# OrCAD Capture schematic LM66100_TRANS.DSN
size E; title: LM66100: 5.5-V, 1.5-A 79mOhm, Low IQ Ideal Diode With; rev: 1.0; note: Datasheet: SLVSEZ8A     EVM: SLVUBL9; note: Input Polarity Protection
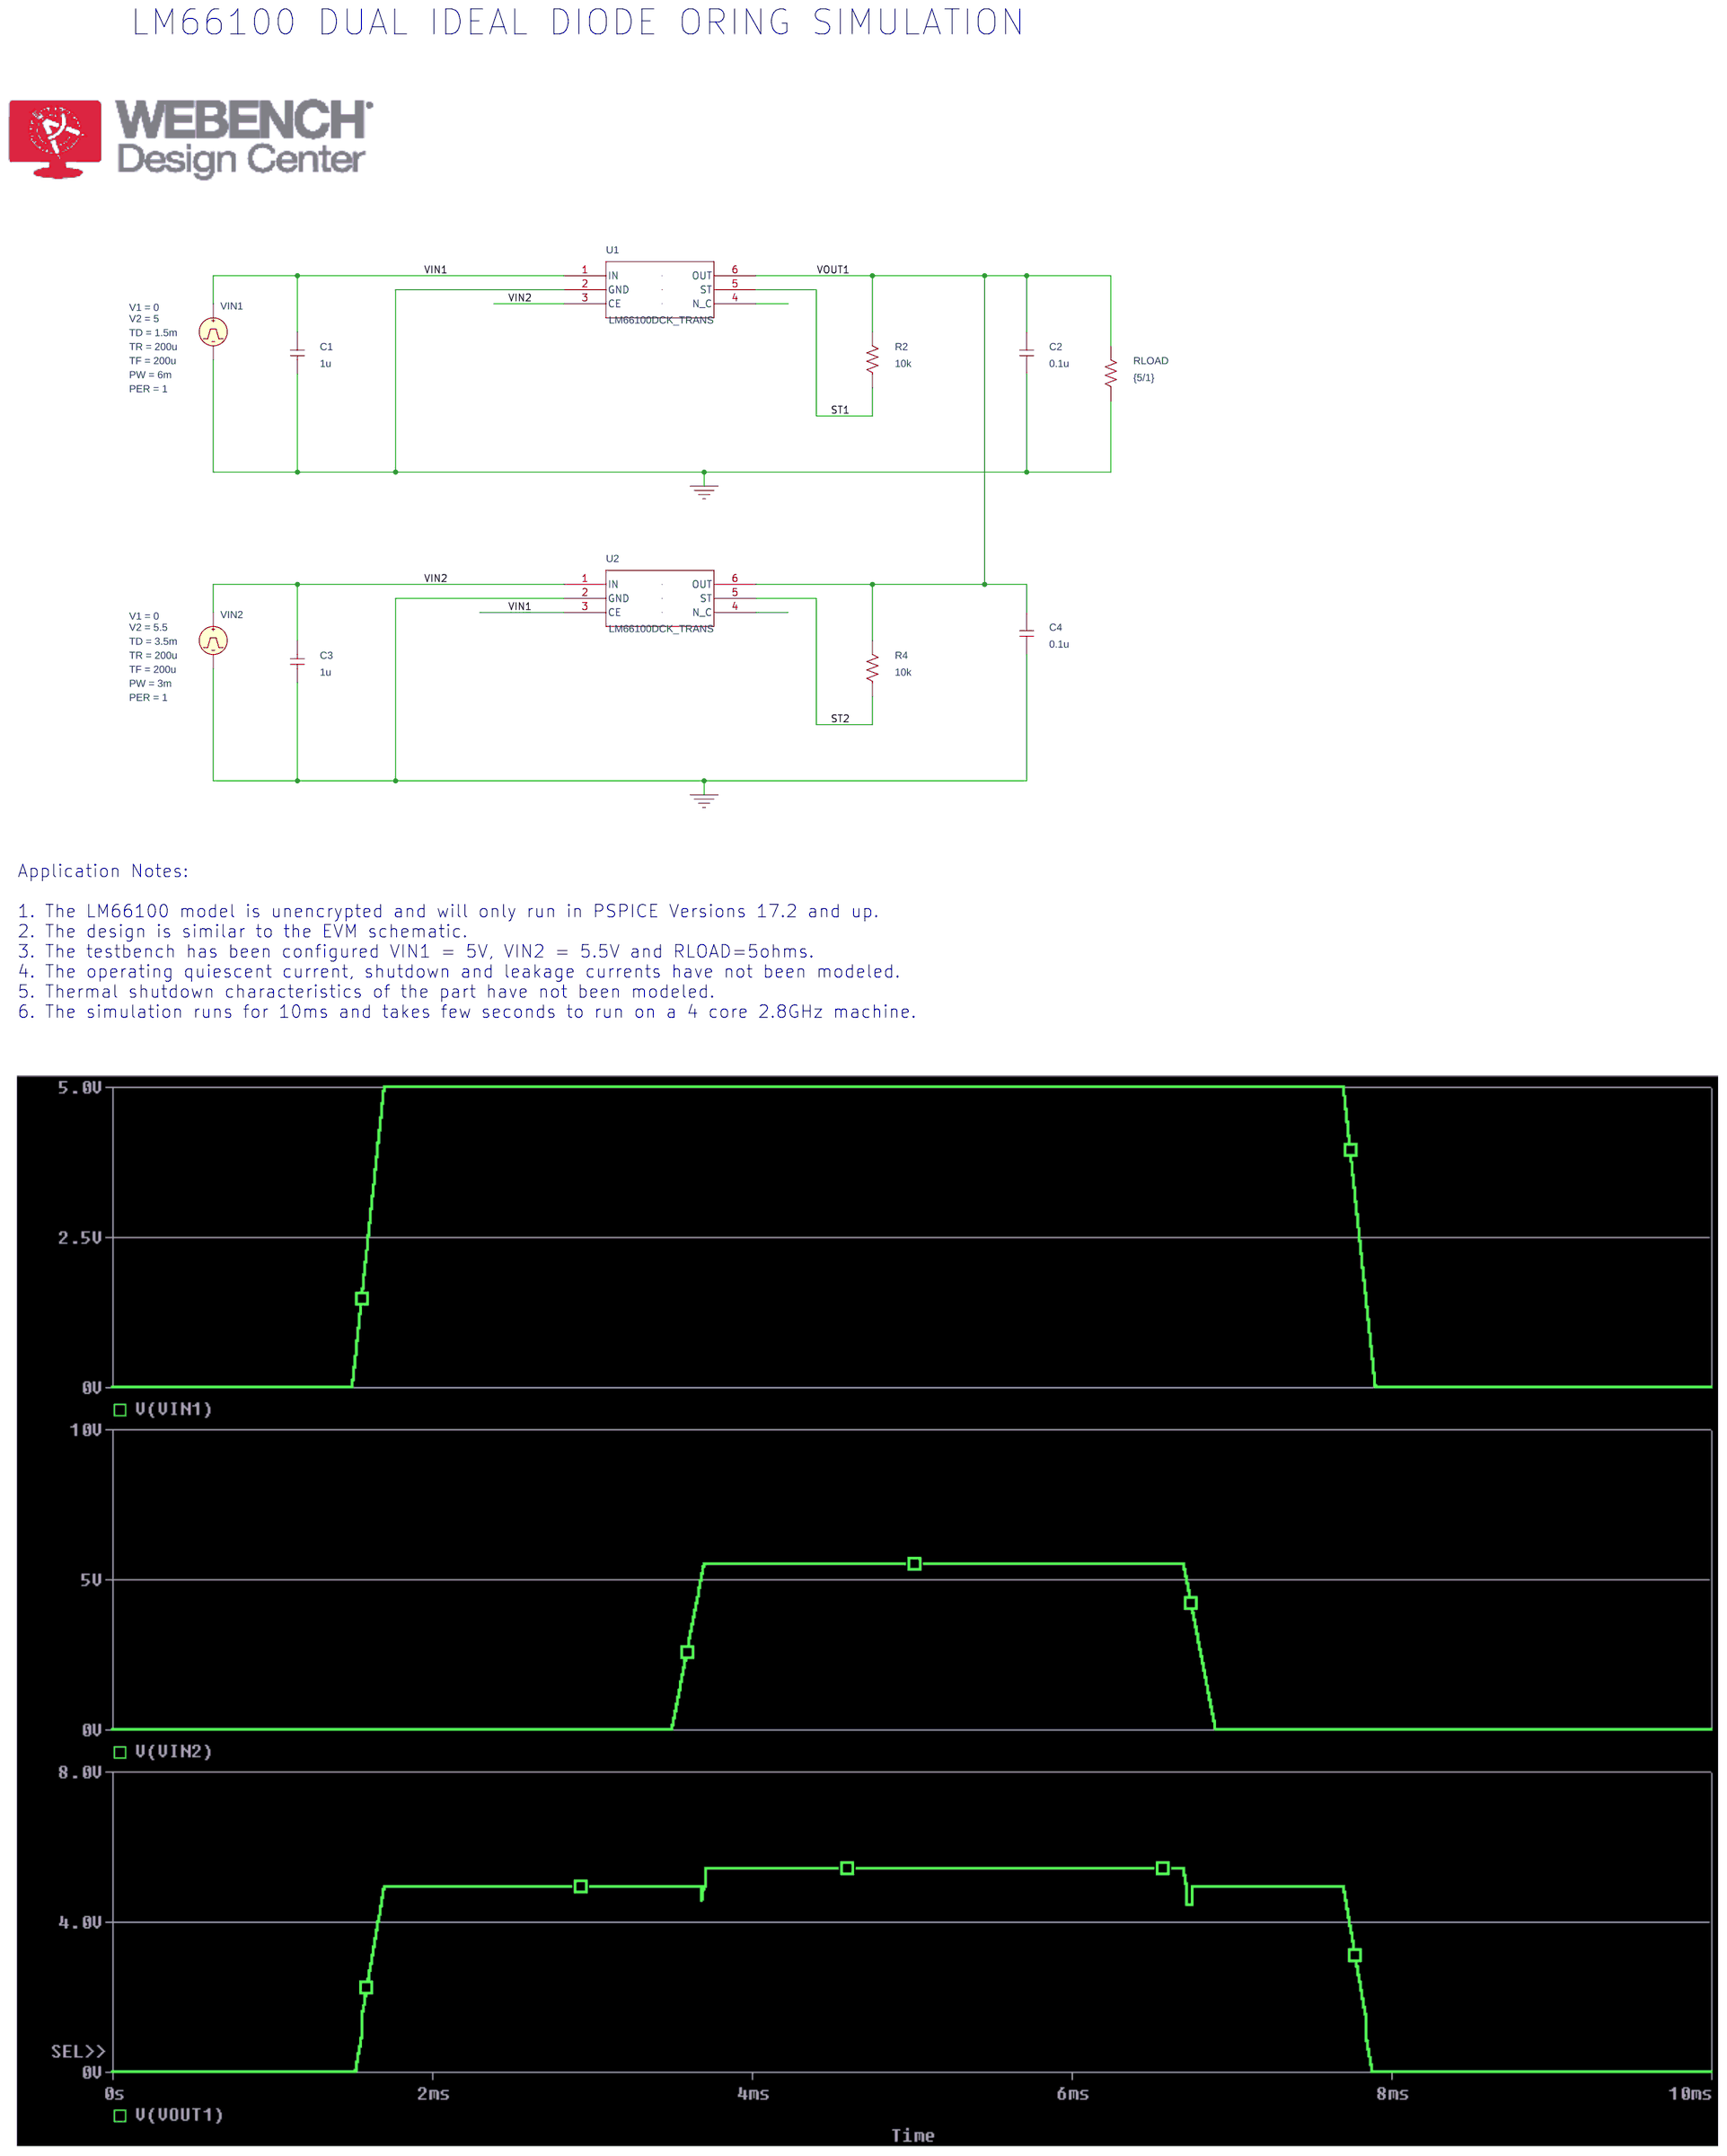
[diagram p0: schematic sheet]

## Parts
C1  1u  [RAD/CK05]
C2  0.1u  [RAD/CK05]
C3  1u  [RAD/CK05]
C4  0.1u  [RAD/CK05]
R2  10k  [AX/RC05]
R4  10k  [AX/RC05]
RLOAD  {5/1}  [AX/RC05]
U1  LM66100DCK_TRANS  [DCK0006A_N]
U2  LM66100DCK_TRANS  [DCK0006A_N]
VIN1  VPULSE
VIN2  VPULSE

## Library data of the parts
C1-C4 = C
R2 R4 RLOAD = R
U1 U2 = LM66100_TRANS
VIN1 = VPULSE: PER: 1; PW: 6m; TD: 1.5m; TF: 200u; TR: 200u; V1: 0; V2: 5
VIN2 = VPULSE: PER: 1; PW: 3m; TD: 3.5m; TF: 200u; TR: 200u; V1: 0; V2: 5.5

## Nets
VIN1: C1.2 U1.1(IN) U2.3(CE) VIN1.1(+)
VIN2: C3.2 U1.3(CE) U2.1(IN) VIN2.1(+)
0: C1.1 C2.1 C3.1 C4.1 RLOAD.1 U1.2(GND) U2.2(GND) VIN1.2(-) VIN2.2(-)
ST1: R2.1 U1.5(ST)
ST2: R4.1 U2.5(ST)
VOUT1: C2.2 C4.2 R2.2 R4.2 RLOAD.2 U1.6(OUT) U2.6(OUT)

Not connected (* = marked no-connect by the designer): U1 4(N_C); U2 4(N_C)

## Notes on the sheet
- LM66100 DUAL IDEAL DIODE ORING SIMULATION
- Application Notes:
  1. The LM66100 model is unencrypted and will only run in PSPICE Versions 17.2 and up.
  2. The design is similar to the EVM schematic.
  3. The testbench has been configured VIN1 = 5V, VIN2 = 5.5V and RLOAD=5ohms.
  4. The operating quiescent current, shutdown and leakage currents have not been modeled.
  5. Thermal shutdown characteristics of the part have not been modeled.
  6. The simulation runs for 10ms and takes few seconds to run on a 4 core 2.8GHz machine.
